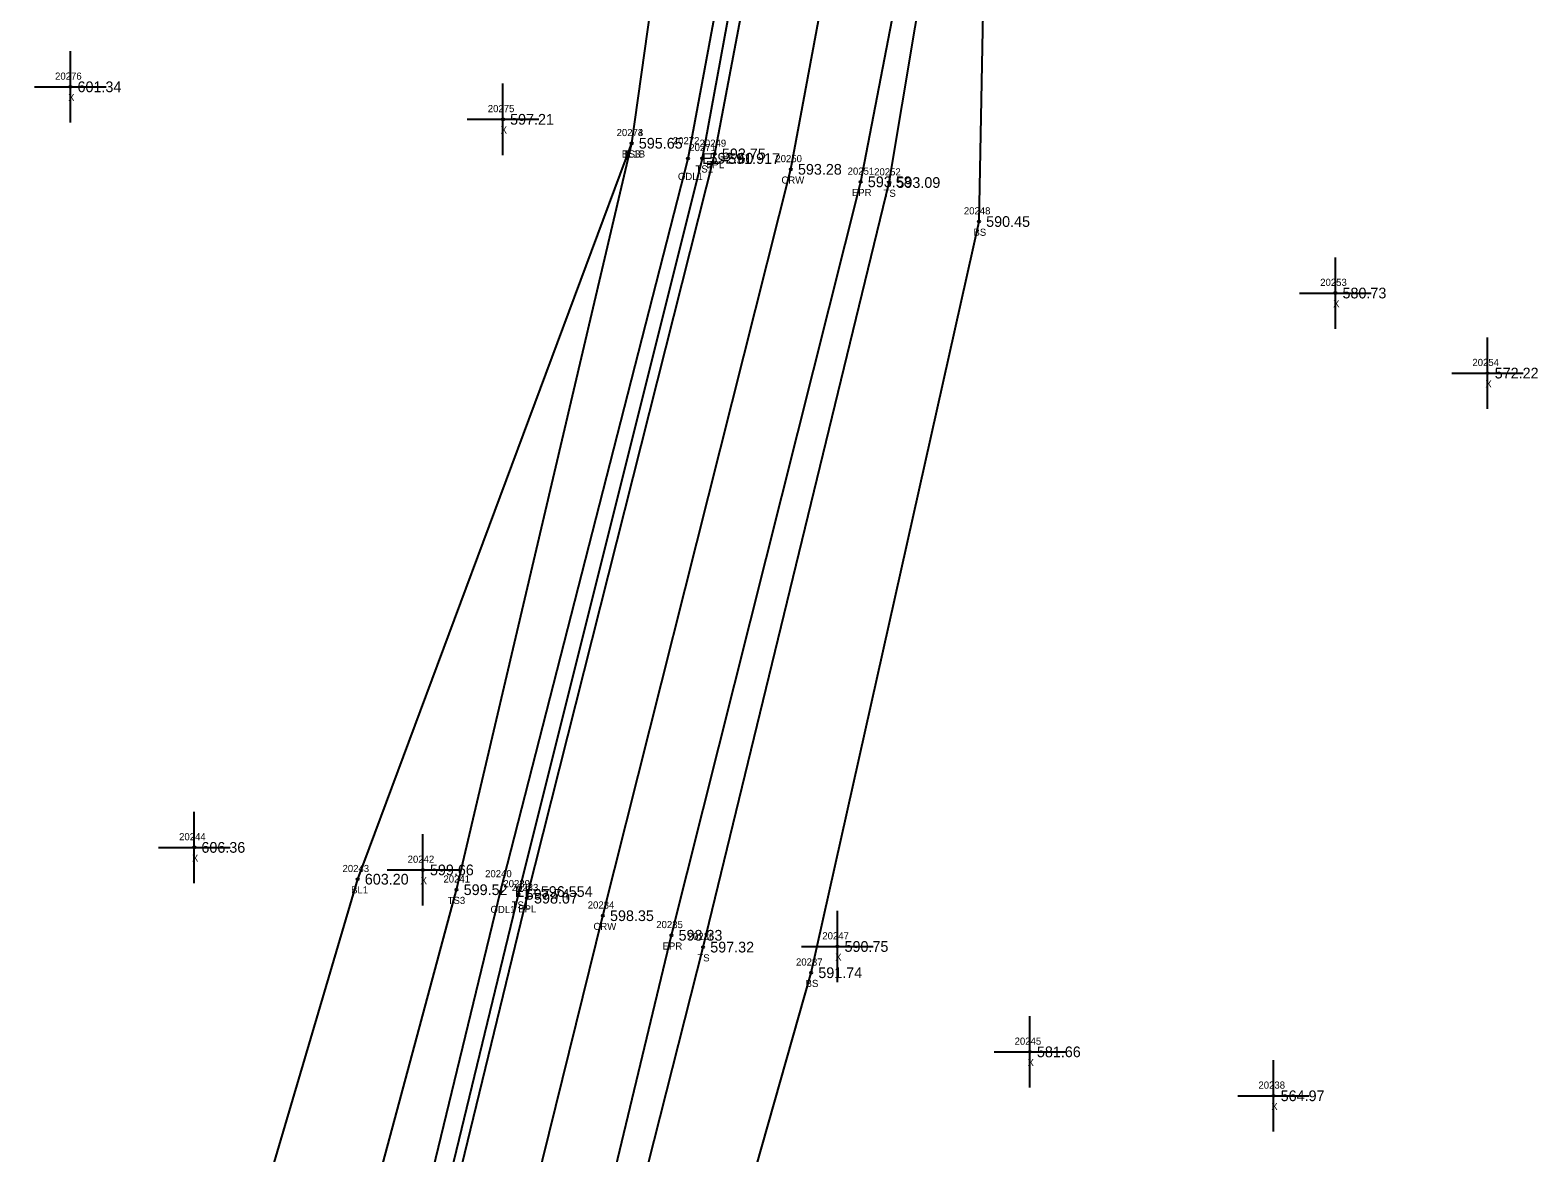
# Model space of a CAD drawing. Extents: x 1695443 to 1696344, y 1087542 to 1090645.
# Drawn here: x 1695929 to 1696140, y 1088464 to 1088621.2 of the extents above; entities that cross this region are included whole.
import ezdxf

# ---------------------------------------------------------------- set-up
doc = ezdxf.new("R2010")
doc.units = 0
for name, color, linetype in [('RD_DTM_BkLn1', 7, 'Continuous'), ('RD_DTM_BkLn2', 7, 'Continuous'), ('RD_DTM_BkLn_txCode', 7, 'Continuous'), ('RD_EX_H2O', 7, 'Continuous'), ('RD_EX_H2O_txCode', 7, 'Continuous'), ('RD_EX_Misc', 7, 'Continuous'), ('RD_EX_Misc_txCode', 7, 'Continuous'), ('RD_EX_Road', 7, 'Continuous'), ('RD_EX_Road_txCode', 7, 'Continuous'), ('RD_EX_TX_H2O_ELEV', 7, 'Continuous'), ('RD_EX_TX_Misc_ELEV', 7, 'Continuous'), ('RD_EX_TX_Road_ELEV', 7, 'Continuous'), ('RD_HC_Survey_ELEV', 7, 'Continuous'), ('RD_HC_Survey_txCode', 7, 'Continuous'), ('RD_SMD_Locator', 7, 'Continuous')]:
    doc.layers.add(name, color=color, linetype=linetype)

msp = doc.modelspace()

# ---------------------------------------------------------------- linework, layer by layer
at = {"layer": 'RD_DTM_BkLn1'}
for points in [[(1695869.23, 1087563.38), (1695882.71, 1087666.87), (1695895.39, 1087768.85), (1695908.05, 1087871.3), (1695919.71, 1087974.19), (1695925.35, 1088026.13), (1695931.27, 1088077.73), (1695937.88, 1088128.75), (1695945.4, 1088182.97), (1695952.48, 1088232.38), (1695961.74, 1088286.36), (1695971.36, 1088336.92), (1695982.91, 1088390.82), (1696009.16, 1088497.22), (1696035.45, 1088601.7), (1696045.5, 1088655.66), (1696049.03, 1088705.78), (1696045.47, 1088756.42), (1696033.82, 1088809.1), (1696016.78, 1088855.71), (1695990.89, 1088906.17), (1695964.41, 1088947.39), (1695931.21, 1088992.88)], [(1695919.84, 1088133.52), (1695913.76, 1088189.35), (1695918.21, 1088235.47), (1695922.76, 1088289.81), (1695929.86, 1088337.9), (1695944.4, 1088398.9), (1695974.86, 1088502.33), (1696013.19, 1088605.35)]]:
    msp.add_lwpolyline(points, dxfattribs=at)
at = {"layer": 'RD_DTM_BkLn2'}
for points in [[(1695957.06, 1088113.83), (1695958.4, 1088124.86), (1695969.72, 1088175.5), (1695984.45, 1088233.12), (1695986.34, 1088280.33), (1695995.02, 1088332.7), (1696009.2, 1088386.54), (1696038.3, 1088489.24), (1696061.78, 1088594.39), (1696062.98, 1088655.37), (1696069.05, 1088704.28), (1696065.26, 1088759.68), (1696052.53, 1088814.08), (1696046.96, 1088869.93), (1696016.66, 1088919.05), (1695997.75, 1088967.45), (1695944.59, 1089014.67), (1695937.23, 1089009.08)], [(1695916.78, 1088084), (1695925.73, 1088132.37), (1695932.55, 1088186.85), (1695940.12, 1088233.39), (1695949.48, 1088288.14), (1695959.7, 1088339.01), (1695971.73, 1088394.21), (1695997.36, 1088500.21), (1696023.08, 1088603.25), (1696032.92, 1088656.94), (1696036.1, 1088705.18), (1696032.76, 1088754.54), (1696021.34, 1088805.78), (1696004.42, 1088850.43), (1695979.2, 1088899.43), (1695947.85, 1088934.07), (1695935.29, 1088941.42), (1695930.1, 1088962.13), (1695923.44, 1088976.06), (1695917.46, 1088980.5), (1695920.03, 1088983.92)], [(1695811.33, 1088056.44), (1695848.8, 1088075.62), (1695896.28, 1088098.14), (1695916.78, 1088084), (1695919.84, 1088133.52), (1695923.64, 1088187.73), (1695930.8, 1088232.96), (1695939.58, 1088289.44), (1695949.3, 1088339.9), (1695960.86, 1088397.31), (1695988.69, 1088500.86), (1696013.19, 1088605.35), (1696020.87, 1088659.75), (1696023.4, 1088706.14), (1696018.3, 1088755.38), (1696009.58, 1088802.31), (1695993.24, 1088846.7), (1695969.88, 1088894.03), (1695962.8, 1088910.68)], [(1695882.6, 1087560.4), (1695895.55, 1087664.54), (1695908.06, 1087766.74), (1695920.67, 1087869.68), (1695933.47, 1087972.17), (1695938.06, 1088020.68), (1695943.39, 1088076.15), (1695950.93, 1088126.12), (1695958.62, 1088180.79), (1695967.59, 1088232.03), (1695975.32, 1088283.22), (1695985.14, 1088336.17), (1695996.59, 1088387.88), (1696023.18, 1088492.82), (1696049.23, 1088599.85), (1696058.32, 1088654.25)]]:
    msp.add_lwpolyline(points, dxfattribs=at)
at = {"layer": 'RD_EX_H2O'}
msp.add_lwpolyline([(1695916.78, 1088084), (1695923.72, 1088132.78), (1695929.91, 1088186.51), (1695936.75, 1088234.45), (1695946.8, 1088289.18), (1695957.47, 1088339.74), (1695969.14, 1088394.61), (1695994.85, 1088500.6), (1696021.07, 1088603.21), (1696031.1, 1088657.25), (1696033.92, 1088705.19), (1696029.81, 1088754.45), (1696018.23, 1088805.15), (1696001.4, 1088849.48), (1695973.58, 1088895.84), (1695962.8, 1088910.68)], dxfattribs=at)
at = {"layer": 'RD_EX_Misc'}
for p, q in [((1695934.67, 1088608.25), (1695934.67, 1088618.25)), ((1695929.67, 1088613.25), (1695939.67, 1088613.25)), ((1695995.18, 1088603.7), (1695995.18, 1088613.7)), ((1695990.18, 1088608.7), (1696000.18, 1088608.7)), ((1696111.63, 1088579.38), (1696111.63, 1088589.38)), ((1696106.63, 1088584.38), (1696116.63, 1088584.38)), ((1696132.92, 1088568.17), (1696132.92, 1088578.17)), ((1696127.92, 1088573.17), (1696137.92, 1088573.17)), ((1695952, 1088501.78), (1695952, 1088511.78)), ((1695983.97, 1088498.63), (1695983.97, 1088508.63)), ((1695947, 1088506.78), (1695957, 1088506.78)), ((1695978.97, 1088503.63), (1695988.97, 1088503.63)), ((1696041.97, 1088487.91), (1696041.97, 1088497.91)), ((1696036.97, 1088492.91), (1696046.97, 1088492.91)), ((1696068.88, 1088473.16), (1696068.88, 1088483.16)), ((1696063.88, 1088478.16), (1696073.88, 1088478.16)), ((1696102.98, 1088467.01), (1696102.98, 1088477.01)), ((1696097.98, 1088472.01), (1696107.98, 1088472.01))]:
    msp.add_line(p, q, dxfattribs=at)
at = {"layer": 'RD_EX_Road'}
for points in [[(1695879.87, 1087561.29), (1695893.33, 1087665.71), (1695905.96, 1087767.16), (1695918.66, 1087869.54), (1695930.87, 1087972.82), (1695936.26, 1088023.68), (1695942.14, 1088076.32), (1695948.07, 1088128.17), (1695955.04, 1088181.4), (1695962.88, 1088230.72), (1695971.68, 1088284.64), (1695982.02, 1088336.12), (1695993.28, 1088388.48), (1696018.75, 1088494.48), (1696045.23, 1088599.95), (1696055.72, 1088654.41), (1696060.15, 1088705.35), (1696055.83, 1088758.02), (1696044.01, 1088812.16), (1696026.4, 1088860.33), (1696000.41, 1088911.48), (1695972.46, 1088953.82), (1695939.48, 1088998.73), (1695931.21, 1088992.88)], [(1695858.19, 1087564.9), (1695871.71, 1087668.82), (1695884.5, 1087774.69), (1695887.48, 1087794.2), (1695897.57, 1087873.43), (1695908.92, 1087975.76), (1695914.49, 1088029.24), (1695917.65, 1088054.8), (1695920.27, 1088079.09), (1695926.98, 1088130.26), (1695934.75, 1088185.09), (1695942.15, 1088234.62), (1695951.36, 1088288.06), (1695961.48, 1088338.41), (1695972.86, 1088394.13), (1695998.53, 1088499.67), (1696024.81, 1088603.86), (1696034.83, 1088656.78)]]:
    msp.add_lwpolyline(points, dxfattribs=at)
at = {"layer": 'RD_SMD_Locator'}
for centre in [(1695934.67, 1088613.25), (1695995.18, 1088608.7), (1696013.19, 1088605.35), (1696013.19, 1088605.35), (1696024.81, 1088603.86), (1696021.07, 1088603.21), (1696023.08, 1088603.25), (1696035.45, 1088601.7), (1696045.23, 1088599.95), (1696049.23, 1088599.85), (1696061.78, 1088594.39), (1696111.63, 1088584.38), (1696132.92, 1088573.17), (1695952, 1088506.78), (1695974.86, 1088502.33), (1695983.97, 1088503.63), (1695988.69, 1088500.86), (1695994.85, 1088500.6), (1695997.36, 1088500.21), (1695998.53, 1088499.67), (1696009.16, 1088497.22), (1696018.75, 1088494.48), (1696023.18, 1088492.82), (1696041.97, 1088492.91), (1696038.3, 1088489.24), (1696068.88, 1088478.16), (1696102.98, 1088472.01)]:
    msp.add_circle(centre, 0.15, dxfattribs=at)

# ---------------------------------------------------------------- texts
at = {"layer": 'RD_DTM_BkLn_txCode'}
for s, p in [('20273', (1696011.08, 1088606.35)), ('20274', (1696011.08, 1088606.35)), ('BL1B', (1696011.8, 1088603.35)), ('TS3', (1696011.95, 1088603.35)), ('20271', (1696021.25, 1088604.25)), ('TS1', (1696022.12, 1088601.25)), ('20252', (1696047.11, 1088600.85)), ('TS', (1696048.43, 1088597.85)), ('20248', (1696059.66, 1088595.39)), ('BS', (1696061, 1088592.39)), ('20243', (1695972.74, 1088503.33)), ('20241', (1695986.86, 1088501.86)), ('BL1', (1695973.94, 1088500.33)), ('20239', (1695995.24, 1088501.21)), ('TS3', (1695987.45, 1088498.86)), ('TS1', (1695996.4, 1088498.21)), ('20236', (1696021.03, 1088493.82)), ('TS', (1696022.38, 1088490.82)), ('20237', (1696036.18, 1088490.24)), ('BS', (1696037.52, 1088487.24))]:
    msp.add_text(s, height=1, dxfattribs=at).set_placement(p)
at = {"layer": 'RD_EX_H2O_txCode'}
for s, p in [('20272', (1696018.95, 1088605.21)), ('ODL1', (1696019.66, 1088600.21)), ('20240', (1695992.69, 1088502.6)), ('ODL1', (1695993.44, 1088497.6))]:
    msp.add_text(s, height=1, dxfattribs=at).set_placement(p)
at = {"layer": 'RD_EX_Misc_txCode'}
for s, p in [('20276', (1695932.53, 1088614.25)), ('X', (1695934.36, 1088611.25)), ('20275', (1695993.06, 1088609.7)), ('X', (1695994.86, 1088606.7)), ('20253', (1696109.51, 1088585.38)), ('X', (1696111.32, 1088582.38)), ('20254', (1696130.8, 1088574.17)), ('X', (1696132.61, 1088571.17)), ('20244', (1695949.88, 1088507.78)), ('X', (1695951.68, 1088504.78)), ('20242', (1695981.85, 1088504.63)), ('X', (1695983.66, 1088501.63)), ('20247', (1696039.86, 1088493.91)), ('X', (1696041.66, 1088490.91)), ('20245', (1696066.76, 1088479.16)), ('X', (1696068.57, 1088476.16)), ('20238', (1696100.87, 1088473.01)), ('X', (1696102.67, 1088470.01))]:
    msp.add_text(s, height=1, dxfattribs=at).set_placement(p)
at = {"layer": 'RD_EX_Road_txCode'}
for s, p in [('20249', (1696022.69, 1088604.86)), ('EPL', (1696023.6, 1088601.86)), ('20251', (1696043.4, 1088600.95)), ('EPR', (1696044, 1088597.95)), ('20233', (1695996.41, 1088500.67)), ('EPL', (1695997.32, 1088497.67)), ('20235', (1696016.63, 1088495.48)), ('EPR', (1696017.52, 1088492.48))]:
    msp.add_text(s, height=1, dxfattribs=at).set_placement(p)
at = {"layer": 'RD_EX_TX_H2O_ELEV'}
for s, p in [('EL=591.917', (1696023.07, 1088602.46)), ('EL=596.554', (1695996.85, 1088499.85))]:
    msp.add_text(s, height=1.5, dxfattribs=at).set_placement(p)
at = {"layer": 'RD_EX_TX_Misc_ELEV'}
for s, p in [('601.34', (1695935.67, 1088612.5)), ('597.21', (1695996.18, 1088607.95)), ('595.65', (1696014.19, 1088604.6)), ('595.65', (1696014.19, 1088604.6)), ('592.60', (1696024.08, 1088602.5)), ('593.09', (1696050.23, 1088599.1)), ('590.45', (1696062.78, 1088593.64)), ('580.73', (1696112.63, 1088583.63)), ('572.22', (1696133.92, 1088572.42)), ('606.36', (1695953, 1088506.03)), ('599.66', (1695984.97, 1088502.88)), ('603.20', (1695975.86, 1088501.58)), ('599.52', (1695989.69, 1088500.11)), ('597.74', (1695998.36, 1088499.46)), ('597.32', (1696024.18, 1088492.07)), ('590.75', (1696042.97, 1088492.16)), ('591.74', (1696039.3, 1088488.49)), ('581.66', (1696069.88, 1088477.41)), ('564.97', (1696103.98, 1088471.26))]:
    msp.add_text(s, height=1.5, dxfattribs=at).set_placement(p)
at = {"layer": 'RD_EX_TX_Road_ELEV'}
for s, p in [('592.75', (1696025.81, 1088603.11)), ('593.58', (1696046.23, 1088599.2)), ('598.07', (1695999.53, 1088498.92)), ('598.33', (1696019.75, 1088493.73))]:
    msp.add_text(s, height=1.5, dxfattribs=at).set_placement(p)
at = {"layer": 'RD_HC_Survey_ELEV'}
for s, p in [('593.28', (1696036.45, 1088600.95)), ('598.35', (1696010.16, 1088496.47))]:
    msp.add_text(s, height=1.5, dxfattribs=at).set_placement(p)
at = {"layer": 'RD_HC_Survey_txCode'}
for s, p in [('20250', (1696033.29, 1088602.7)), ('CRW', (1696034.14, 1088599.7)), ('20234', (1696007.04, 1088498.22)), ('CRW', (1696007.84, 1088495.22))]:
    msp.add_text(s, height=1, dxfattribs=at).set_placement(p)

doc.saveas('drawing.dxf')
